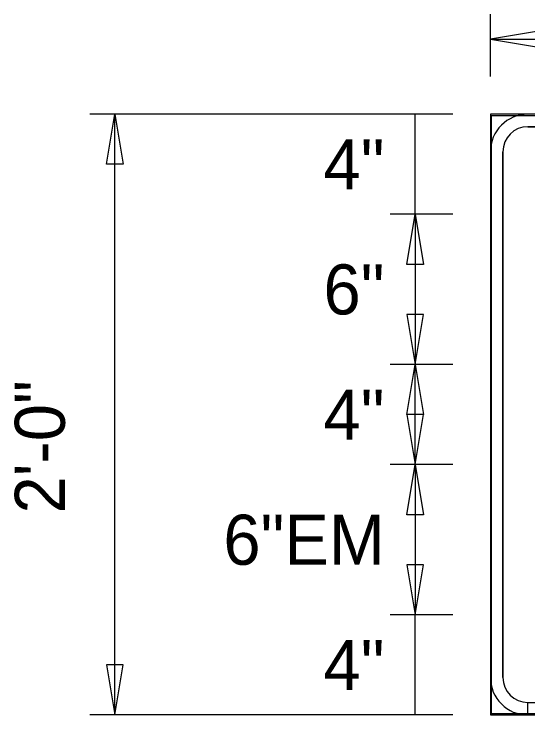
# Model space of a CAD drawing. Extents: x 1374 to 1480, y 568 to 638.
# Drawn here: x 1413.272 to 1414.983, y 635.119 to 637.453 of the extents above; entities that cross this region are included whole.
import ezdxf

# ---------------------------------------------------------------- set-up
doc = ezdxf.new("R2010")
doc.units = 0
for name, color, linetype in [('GSBWFill', 7, 'Continuous'), ('GSColorFill', 7, 'Continuous'), ('GSDims', 7, 'Continuous'), ('GSOutline', 7, 'Continuous')]:
    doc.layers.add(name, color=color, linetype=linetype)

msp = doc.modelspace()

# ---------------------------------------------------------------- linework, layer by layer
at = {"layer": 'GSBWFill'}
for p, q in [((1423.8581, 637.1193), (1414.8581, 637.1193)), ((1414.8581, 637.1193), (1414.8581, 635.1193)), ((1423.7331, 637.1193), (1414.9831, 637.1193)), ((1414.9831, 637.0776), (1423.7331, 637.0776)), ((1414.8581, 636.9943), (1414.8581, 635.2443)), ((1414.8998, 635.2443), (1414.8998, 636.9943)), ((1414.9831, 635.1193), (1414.9831, 635.161)), ((1414.8581, 635.1193), (1423.8581, 635.1193))]:
    msp.add_line(p, q, dxfattribs=at)
for centre, radius, start, end in [((1414.9831, 636.9943), 0.125, 90, 180), ((1414.9831, 636.9943), 0.0833, 90, 180), ((1414.9831, 635.2443), 0.125, 180, 270), ((1414.9831, 635.2443), 0.0833, 180, 270)]:
    msp.add_arc(centre, radius, start, end, dxfattribs=at)
at = {"layer": 'GSColorFill'}
for p, q in [((1423.8581, 637.1193), (1414.8581, 637.1193)), ((1414.8581, 637.1193), (1414.8581, 635.1193)), ((1423.8581, 637.1193), (1414.8581, 637.1193)), ((1414.8581, 637.1193), (1414.8581, 635.1235)), ((1423.7331, 637.1193), (1414.9831, 637.1193)), ((1414.8623, 635.1235), (1414.8623, 637.1151)), ((1414.8623, 637.1151), (1423.854, 637.1151)), ((1414.9831, 637.0776), (1423.7331, 637.0776)), ((1414.8581, 636.9943), (1414.8581, 635.2443)), ((1414.8998, 635.2443), (1414.8998, 636.9943)), ((1414.9831, 635.1193), (1414.9831, 635.161)), ((1414.8581, 635.1235), (1414.8623, 635.1235)), ((1423.854, 635.1235), (1414.8581, 635.1235)), ((1414.8581, 635.1235), (1414.8581, 635.1193)), ((1414.8581, 635.1193), (1423.8581, 635.1193)), ((1414.8581, 635.1193), (1423.8581, 635.1193))]:
    msp.add_line(p, q, dxfattribs=at)
for centre, radius, start, end in [((1414.9831, 636.9943), 0.125, 90, 180), ((1414.9831, 636.9943), 0.0833, 90, 180), ((1414.9831, 635.2443), 0.125, 180, 270), ((1414.9831, 635.2443), 0.0833, 180, 270)]:
    msp.add_arc(centre, radius, start, end, dxfattribs=at)
at = {"layer": 'GSDims'}
for p, q in [((1414.8581, 637.2443), (1414.8581, 637.4526)), ((1414.8581, 637.3693), (1423.8581, 637.3693)), ((1414.8581, 637.2443), (1414.8581, 637.2443)), ((1413.7331, 637.1193), (1413.5248, 637.1193)), ((1413.6081, 635.1193), (1413.6081, 637.1193)), ((1414.7331, 637.1193), (1413.7331, 637.1193)), ((1414.7331, 637.1193), (1414.5248, 637.1193)), ((1414.6081, 636.786), (1414.6081, 637.1193)), ((1414.7331, 636.786), (1414.5248, 636.786)), ((1414.7331, 636.786), (1414.5248, 636.786)), ((1414.6081, 636.786), (1414.6081, 636.286)), ((1414.7331, 636.286), (1414.5248, 636.286)), ((1414.7331, 636.286), (1414.5248, 636.286)), ((1414.6081, 635.9526), (1414.6081, 636.286)), ((1414.7331, 635.9526), (1414.5248, 635.9526)), ((1414.7331, 635.9526), (1414.5248, 635.9526)), ((1414.6081, 635.9526), (1414.6081, 635.4526)), ((1414.7331, 635.4526), (1414.5248, 635.4526)), ((1414.7331, 635.4526), (1414.5248, 635.4526)), ((1414.6081, 635.1193), (1414.6081, 635.4526)), ((1413.7331, 635.1193), (1413.5248, 635.1193)), ((1414.7331, 635.1193), (1413.7331, 635.1193)), ((1414.7331, 635.1193), (1414.5248, 635.1193))]:
    msp.add_line(p, q, dxfattribs=at)
for points in [[(1414.8581, 637.3693), (1415.0248, 637.3415), (1415.0248, 637.3971)], [(1413.6081, 637.1193), (1413.6359, 636.9526), (1413.5803, 636.9526)], [(1414.6081, 636.786), (1414.6359, 636.6193), (1414.5803, 636.6193)], [(1414.6081, 636.286), (1414.6359, 636.4526), (1414.5803, 636.4526)], [(1414.6081, 636.286), (1414.6359, 636.1193), (1414.5803, 636.1193)], [(1414.6081, 635.9526), (1414.6359, 636.1193), (1414.5803, 636.1193)], [(1414.6081, 635.9526), (1414.6359, 635.786), (1414.5803, 635.786)], [(1414.6081, 635.4526), (1414.6359, 635.6193), (1414.5803, 635.6193)], [(1413.6081, 635.1193), (1413.6359, 635.286), (1413.5803, 635.286)]]:
    msp.add_lwpolyline(points, close=True, dxfattribs=at)
at = {"layer": 'GSOutline'}
for p, q in [((1423.8581, 637.1193), (1414.8581, 637.1193)), ((1414.8581, 637.1193), (1414.8581, 635.1193)), ((1423.7331, 637.1193), (1414.9831, 637.1193)), ((1423.7331, 637.0776), (1414.9831, 637.0776)), ((1414.8581, 636.9943), (1414.8581, 635.2443)), ((1414.8998, 636.9943), (1414.8998, 635.2443)), ((1414.9831, 635.161), (1423.7331, 635.161)), ((1414.8581, 635.1193), (1423.8581, 635.1193)), ((1414.9831, 635.1193), (1423.7331, 635.1193))]:
    msp.add_line(p, q, dxfattribs=at)
for centre, radius, start, end in [((1414.9831, 636.9943), 0.125, 90, 180), ((1414.9831, 636.9943), 0.0833, 90, 180), ((1414.9831, 635.2443), 0.125, 180, 270), ((1414.9831, 635.2443), 0.0833, 180, 270)]:
    msp.add_arc(centre, radius, start, end, dxfattribs=at)

# ---------------------------------------------------------------- texts
at = {"layer": 'GSDims'}
for s, p in [('4"', (1414.3026, 636.8693)), ('6"', (1414.3026, 636.4526)), ('4"', (1414.3026, 636.036)), ('6"EM', (1413.9692, 635.6193)), ('4"', (1414.3026, 635.2026))]:
    msp.add_text(s, height=0.16667, dxfattribs=at).set_placement(p)
msp.add_text('2\'-0"', height=0.16667, rotation=90, dxfattribs=at).set_placement((1413.4415, 635.7899))

doc.saveas('drawing.dxf')
